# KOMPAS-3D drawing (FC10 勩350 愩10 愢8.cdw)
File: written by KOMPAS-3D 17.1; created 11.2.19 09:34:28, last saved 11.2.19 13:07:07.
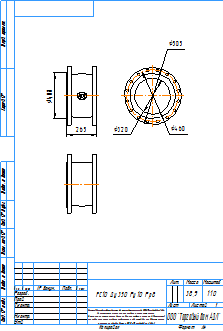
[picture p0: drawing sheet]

Sheet 1: A4, portrait

Title block, sheet 1: name: FC10 Ду350 Ру10 Рр8; mass: 38,9; sheets: 1; sheet format: A4; stored path: \\adlc.lan\data\АДЛ_ПКД\3D-модели\ADL production\Гибкие вставки серии FC\FC10\KOMPAS 2D\FC10 Ду350 Ру10 Рр8.cdw

Views: Вид 1
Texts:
  kka
  adl
  Рама для чертежей
  Лит-Масса-Масштаб
  Материал-Предприятие
  Масштаб
  Изм.
  Лист
  № докум.
  Подп.
  Дата
  Лит.
  Разраб.
  Пров.
  Т.контр.
  Листов
  Внимание! Данный продукт является объектом авторского права ООО «Торговый Дом АДЛ».
  Запрещается изменение, копирование, распространение
  (в том числе путем копирования на другие сайты и ресурсы в Интернете)
  или любое иное использование информации и объектов без предварительного
  согласия правообладателя (ООО «Торговый Дом АДЛ»).
  Н.контр.
  Утв.
  ООО "Торговый дом АДЛ"
  Изменение
  Номер документа
  Подпись
  Обозначение документа
  Наименование изделия
  Масса изделия по ГОСТ 2.109-73
  Порядковый номер листа
  Общее количество листов в документе
  Характер работы, выполненной лицом, подписавшим документ
  Наименование или индекс предприятия, выпускающего документ
  Инв. № подл.
  Подп. и дата
  Взам. инв. №
  Инв. № дубл.
  Инвентарный номер подлинника по ГОСТ 2.501-68
  Подпись принявшего подлинник в отдел технической документации
  Инвентарный номер подлинника, взамен которого выпущен данный подлинник
  Инвентарный номер дубликата по ГОСТ 2.502-68
  Подпись принявшего дубликат в отдел технической документации
  Справ. №
  Перв. примен.
  Обозначение документа, взамен или на основании которого выпущен данный документ
  Обозначение документа, в котором впервые записан данный документ
  Подпись лица, копировавшего чертеж
  Обозначение формата листа
  !Рама для чертежа
Dimensions and other numbers on the sheet: 265; 408; 320; 460; 505; 1:10; 1; 38,9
